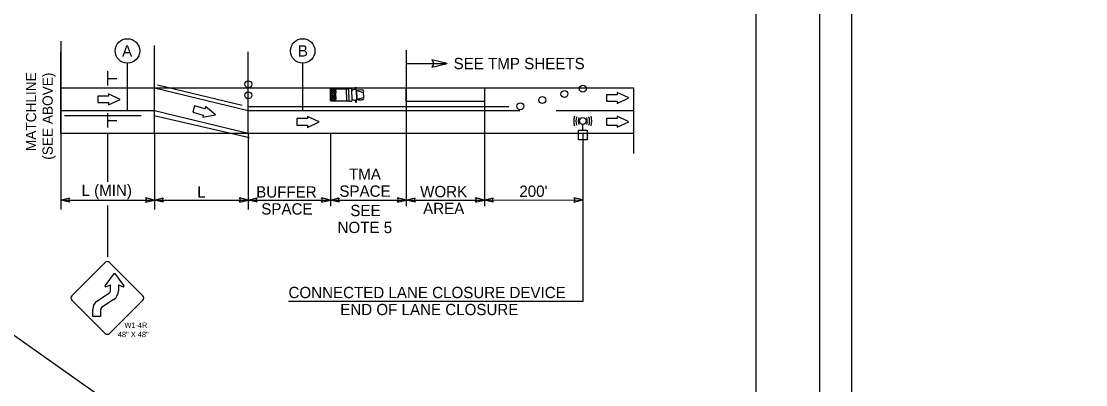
# Model space of a CAD drawing. Extents: x 1379436 to 1387057, y 792703 to 795604.
# Drawn here: x 1381631 to 1382883, y 793820 to 794247 of the extents above; entities that cross this region are included whole.
import ezdxf

# ---------------------------------------------------------------- set-up
doc = ezdxf.new("R2010")
doc.units = 0
for name, color, linetype in [('Default', 7, 'Continuous'), ('DEV BORDER CELL', 7, 'Continuous'), ('DEV DIRECTION OF TRAFFIC FLOW ARROW CELL', 7, 'Continuous'), ('DEV DRUM PLAN VIEW CELL', 7, 'Continuous'), ('DEV LINE TERMINATOR TYPE 3 CELL', 7, 'Continuous'), ('DEV TRUCK MOUNTED IMPACT ATTENUATOR CELL', 7, 'Continuous'), ('Drum Linestyle V8i', 7, 'Continuous'), ('Gray Area Fill Shapes', 7, 'Continuous'), ('Prop Mkg Skp Wht', 7, 'Continuous'), ('Prop Mkg Solid White Lane Line', 7, 'Continuous'), ('Prop Mkg Solid Yellow Edge Line', 7, 'Continuous'), ('Scratch_Level_0', 7, 'Continuous'), ('Scratch_Level_5', 7, 'Continuous'), ('Sheet Plot Border Outside CELL', 7, 'Continuous'), ('TCP Linework', 7, 'Continuous'), ('Text', 7, 'Continuous'), ('WS W1-4R CELL', 7, 'Continuous')]:
    doc.layers.add(name, color=color, linetype=linetype)

msp = doc.modelspace()

# ---------------------------------------------------------------- linework, layer by layer
at = {"layer": 'Default'}
for p, q in [((1379436.3, 795421.7), (1382883.5, 792987.4)), ((1381677.5, 794223.8), (1381677.5, 794060.7)), ((1382084.1, 794213.1), (1382084.1, 794153)), ((1382084.1, 794205.6), (1382084.1, 794142.3)), ((1381756, 794142.3), (1381756, 794198)), ((1381962.2, 794142.3), (1381962.2, 794198))]:
    msp.add_line(p, q, dxfattribs=at)
for centre in [(1381756, 794212.4), (1381962.2, 794212.4)]:
    msp.add_circle(centre, 14.4, dxfattribs=at)
at = {"layer": 'DEV BORDER CELL'}
msp.add_lwpolyline([(1382570.8, 794844.7), (1380320.7, 794844.7), (1380320.7, 793269.7), (1382570.8, 793269.7)], close=True, dxfattribs=at)
at = {"layer": 'DEV DIRECTION OF TRAFFIC FLOW ARROW CELL'}
for p, q in [((1381747.6, 794155.4), (1381733.8, 794161.9)), ((1381733.8, 794161.9), (1381733.8, 794159.2)), ((1382346, 794157), (1382332.2, 794163.5)), ((1382332.2, 794163.5), (1382332.2, 794160.9)), ((1381733.8, 794159.2), (1381721, 794159.3)), ((1381721, 794159.3), (1381721, 794151.5)), ((1381721, 794151.5), (1381733.8, 794151.5)), ((1381733.8, 794148.9), (1381747.6, 794155.4)), ((1381733.8, 794151.5), (1381733.8, 794148.9)), ((1382332.2, 794160.9), (1382319.5, 794160.9)), ((1382319.5, 794160.9), (1382319.5, 794153.2)), ((1382319.5, 794153.2), (1382332.2, 794153.2)), ((1382332.2, 794150.5), (1382346, 794157)), ((1382332.2, 794153.2), (1382332.2, 794150.5)), ((1381835, 794147.7), (1381833, 794140.3)), ((1381833, 794140.3), (1381845.3, 794136.9)), ((1381847.3, 794144.4), (1381835, 794147.7)), ((1381844.7, 794134.4), (1381859.6, 794137.1)), ((1381845.3, 794136.9), (1381844.7, 794134.4)), ((1381848, 794146.9), (1381847.3, 794144.4)), ((1381859.6, 794137.1), (1381848, 794146.9)), ((1381968, 794132.7), (1381955.2, 794132.7)), ((1381955.2, 794132.7), (1381955.2, 794125)), ((1381955.2, 794125), (1381968, 794125)), ((1381981.7, 794128.8), (1381968, 794135.3)), ((1381968, 794135.3), (1381968, 794132.7)), ((1381968, 794122.4), (1381981.7, 794128.8)), ((1381968, 794125), (1381968, 794122.4)), ((1382332.2, 794132.9), (1382319.5, 794132.9)), ((1382319.5, 794132.9), (1382319.5, 794125.2)), ((1382319.5, 794125.2), (1382332.2, 794125.2)), ((1382346, 794129.1), (1382332.2, 794135.6)), ((1382332.2, 794135.6), (1382332.2, 794132.9)), ((1382332.2, 794122.6), (1382346, 794129.1)), ((1382332.2, 794125.2), (1382332.2, 794122.6))]:
    msp.add_line(p, q, dxfattribs=at)
at = {"layer": 'DEV DRUM PLAN VIEW CELL'}
for centre in [(1381898.2, 794173.2), (1381898.2, 794173.2), (1381898.2, 794160.2), (1381898.2, 794160.2), (1382270.2, 794161.8), (1382270.2, 794161.8), (1382291.8, 794167.9), (1382291.8, 794167.9), (1382218.3, 794147.2), (1382218.3, 794147.2), (1382244.3, 794154.5), (1382244.3, 794154.5)]:
    msp.add_circle(centre, 4.08, dxfattribs=at)
at = {"layer": 'DEV LINE TERMINATOR TYPE 3 CELL'}
for points in [[(1382114.2, 794193.1), (1382132, 794197.6), (1382114.2, 794202)], [(1382114.2, 794193.1), (1382132, 794197.6), (1382114.2, 794202)], [(1381687.9, 794034.3), (1381677.5, 794036.9), (1381687.9, 794039.5)], [(1381687.9, 794034.3), (1381677.5, 794036.9), (1381687.9, 794039.5)], [(1381777.4, 794034.3), (1381787.8, 794036.9), (1381777.4, 794039.5)], [(1381777.4, 794034.3), (1381787.8, 794036.9), (1381777.4, 794039.5)], [(1381798.2, 794034.3), (1381787.8, 794036.9), (1381798.2, 794039.5)], [(1381798.2, 794034.3), (1381787.8, 794036.9), (1381798.2, 794039.5)], [(1381887.8, 794034.3), (1381898.2, 794036.9), (1381887.8, 794039.5)], [(1381887.8, 794034.3), (1381898.2, 794036.9), (1381887.8, 794039.5)], [(1381908.5, 794034.3), (1381898.2, 794036.9), (1381908.5, 794039.5)], [(1381908.5, 794034.3), (1381898.2, 794036.9), (1381908.5, 794039.5)], [(1381984.4, 794034.3), (1381994.8, 794036.9), (1381984.4, 794039.5)], [(1381984.4, 794034.3), (1381994.8, 794036.9), (1381984.4, 794039.5)], [(1382005.2, 794034.3), (1381994.8, 794036.9), (1382005.2, 794039.5)], [(1382005.2, 794034.3), (1381994.8, 794036.9), (1382005.2, 794039.5)], [(1382073.7, 794034.3), (1382084.1, 794036.9), (1382073.7, 794039.5)], [(1382073.7, 794034.3), (1382084.1, 794036.9), (1382073.7, 794039.5)], [(1382094.5, 794034.3), (1382084.1, 794036.9), (1382094.5, 794039.5)], [(1382094.5, 794034.3), (1382084.1, 794036.9), (1382094.5, 794039.5)], [(1382165.6, 794034.3), (1382176, 794036.9), (1382165.6, 794039.5)], [(1382165.6, 794034.3), (1382176, 794036.9), (1382165.6, 794039.5)], [(1382186.4, 794034.3), (1382176, 794036.9), (1382186.4, 794039.5)], [(1382186.4, 794034.3), (1382176, 794036.9), (1382186.4, 794039.5)], [(1382281.4, 794034.4), (1382291.8, 794037), (1382281.4, 794039.5)], [(1382281.4, 794034.4), (1382291.8, 794037), (1382281.4, 794039.5)]]:
    msp.add_lwpolyline(points, dxfattribs=at)
for centre, radius, start, end in [((1382110.3, 794197.6), 5.92, 311.3264, 48.6736), ((1382110.3, 794197.6), 5.92, 311.3264, 48.6736), ((1381690.1, 794036.9), 3.46, 131.3264, 228.6736), ((1381690.1, 794036.9), 3.46, 131.3264, 228.6736), ((1381775.1, 794036.9), 3.46, 311.3264, 48.6736), ((1381775.1, 794036.9), 3.46, 311.3264, 48.6736), ((1381800.5, 794036.9), 3.46, 131.3264, 228.6736), ((1381800.5, 794036.9), 3.46, 131.3264, 228.6736), ((1381885.5, 794036.9), 3.46, 311.3264, 48.6736), ((1381885.5, 794036.9), 3.46, 311.3264, 48.6736), ((1381910.8, 794036.9), 3.46, 131.3264, 228.6736), ((1381910.8, 794036.9), 3.46, 131.3264, 228.6736), ((1381982.1, 794036.9), 3.46, 311.3264, 48.6736), ((1381982.1, 794036.9), 3.46, 311.3264, 48.6736), ((1382007.5, 794036.9), 3.46, 131.3264, 228.6736), ((1382007.5, 794036.9), 3.46, 131.3264, 228.6736), ((1382071.4, 794036.9), 3.46, 311.3264, 48.6736), ((1382071.4, 794036.9), 3.46, 311.3264, 48.6736), ((1382096.8, 794036.9), 3.46, 131.3264, 228.6736), ((1382096.8, 794036.9), 3.46, 131.3264, 228.6736), ((1382163.3, 794036.9), 3.46, 311.3264, 48.6736), ((1382163.3, 794036.9), 3.46, 311.3264, 48.6736), ((1382188.7, 794036.9), 3.46, 131.3264, 228.6736), ((1382188.7, 794036.9), 3.46, 131.3264, 228.6736), ((1382279.1, 794037), 3.46, 311.3264, 48.6736), ((1382279.1, 794037), 3.46, 311.3264, 48.6736)]:
    msp.add_arc(centre, radius, start, end, dxfattribs=at)
at = {"layer": 'DEV TRUCK MOUNTED IMPACT ATTENUATOR CELL'}
for p, q in [((1381994.8, 794167.7), (1382016.6, 794167.7)), ((1381994.8, 794153.6), (1381994.8, 794167.7)), ((1381994.8, 794167.7), (1381994.8, 794165)), ((1381994.8, 794167.7), (1381994.8, 794165)), ((1381994.8, 794167.7), (1381994.8, 794165)), ((1381994.8, 794167.7), (1381994.8, 794165)), ((1381994.8, 794165), (1381994.8, 794167.7)), ((1381994.8, 794167.7), (1381997.2, 794167.7)), ((1381997.2, 794167.7), (1381994.8, 794165)), ((1381994.8, 794162.8), (1381999.2, 794167.7)), ((1382001.1, 794167.7), (1381994.8, 794160.6)), ((1381994.8, 794160.6), (1381994.8, 794162.8)), ((1381996.8, 794160.6), (1382001.1, 794165.5)), ((1382001.1, 794163.3), (1381998.7, 794160.6)), ((1381999.2, 794167.7), (1382001.1, 794167.7)), ((1382001.1, 794153.6), (1382001.1, 794167.7)), ((1382001.1, 794165.5), (1382001.1, 794163.3)), ((1382013.7, 794160.6), (1382013.7, 794167.7)), ((1382016.6, 794160.6), (1382016.6, 794167.7)), ((1382020, 794160.6), (1382020, 794167.7)), ((1382024.5, 794168.1), (1382024.5, 794169.9)), ((1382024.8, 794166.4), (1382024.8, 794169.9)), ((1382025, 794166.4), (1382025, 794169.9)), ((1382025.6, 794160.6), (1382025.6, 794165.7)), ((1382026.1, 794165.7), (1382033.7, 794163.6)), ((1382026.1, 794160.6), (1382026.1, 794165.7)), ((1382033.7, 794160.6), (1382033.7, 794163.6)), ((1381994.8, 794160.6), (1382001.1, 794153.6)), ((1381994.8, 794158.5), (1381994.8, 794160.6)), ((1381999.2, 794153.6), (1381994.8, 794158.5)), ((1381994.8, 794156.3), (1381994.8, 794153.6)), ((1381997.2, 794153.6), (1381994.8, 794156.3)), ((1381994.8, 794153.6), (1382016.6, 794153.6)), ((1381994.8, 794153.6), (1381997.2, 794153.6)), ((1382001.1, 794155.8), (1381996.8, 794160.6)), ((1381998.7, 794160.6), (1382001.1, 794158)), ((1382001.1, 794153.6), (1381999.2, 794153.6)), ((1382001.1, 794158), (1382001.1, 794155.8)), ((1382013.7, 794160.6), (1382013.7, 794153.6)), ((1382016.6, 794160.6), (1382016.6, 794153.6)), ((1382020, 794160.6), (1382020, 794153.6)), ((1382024.5, 794153.1), (1382024.5, 794151.5)), ((1382024.8, 794154.8), (1382024.8, 794151.5)), ((1382025, 794154.8), (1382025, 794151.5)), ((1382025.6, 794160.6), (1382025.6, 794155.5)), ((1382026.1, 794160.6), (1382026.1, 794155.5)), ((1382026.1, 794155.5), (1382033.7, 794157.6)), ((1382033.7, 794160.6), (1382033.7, 794157.6))]:
    msp.add_line(p, q, dxfattribs=at)
for centre in [(1382031.9, 794164.6), (1382031.9, 794156.6)]:
    msp.add_arc(centre, 2.12, 331.8801, 28.1199, dxfattribs=at)
for centre, major_axis, ratio, start_param, end_param in [((1382018.3, 794167.7), (1.67, 0), 0.269913, 0, 3.141593), ((1382022.8, 794165.4), (2.8, 0.35), 0.503092, 0, 3.141593), ((1382029.9, 794165.7), (3.82, -0.04), 0.2034, 0, 3.141593), ((1382018.3, 794153.6), (1.67, 0), 0.269913, 3.141593, 6.283185), ((1382022.8, 794155.9), (2.8, -0.35), 0.503092, 3.141593, 6.283185), ((1382029.9, 794155.6), (3.82, 0.04), 0.2034, 3.141593, 6.283185)]:
    msp.add_ellipse(centre, major_axis=major_axis, ratio=ratio, start_param=start_param, end_param=end_param, dxfattribs=at)
at = {"layer": 'Drum Linestyle V8i'}
for p, q in [((1381791.4, 794172.5), (1381891.1, 794148.4)), ((1381681.8, 794136.4), (1381772.2, 794136.5)), ((1381787.6, 794136.3), (1381899.8, 794110.3))]:
    msp.add_line(p, q, dxfattribs=at)
msp.add_lwpolyline([(1381898.2, 794146.8), (1382204.8, 794147)], dxfattribs=at)
at = {"layer": 'Gray Area Fill Shapes'}
msp.add_lwpolyline([(1382084.1, 794168.9), (1382176, 794168.9), (1382176, 794153), (1382084.1, 794153)], close=True, dxfattribs=at)
at = {"layer": 'Prop Mkg Skp Wht'}
for p, q in [((1381677.5, 794142.3), (1381677.5, 794142.3)), ((1382260.5, 794142.3), (1382351.6, 794142.3))]:
    msp.add_line(p, q, dxfattribs=at)
at = {"layer": 'Prop Mkg Solid White Lane Line'}
for p, q in [((1381677.5, 794142.3), (1381787.8, 794142.3)), ((1381787.8, 794142.3), (1381898, 794115.7)), ((1381677.5, 794115.7), (1382351.6, 794115.7))]:
    msp.add_line(p, q, dxfattribs=at)
at = {"layer": 'Prop Mkg Solid Yellow Edge Line'}
for p, q in [((1381677.5, 794168.9), (1382351.6, 794168.9)), ((1381787.8, 794168.9), (1381898.2, 794142.3)), ((1381898.2, 794142.3), (1382217.7, 794142.3))]:
    msp.add_line(p, q, dxfattribs=at)
at = {"layer": 'Scratch_Level_0'}
msp.add_line((1382351.6, 794168.9), (1382351.6, 794091.8), dxfattribs=at)
msp.add_lwpolyline([(1382495.8, 794769.7), (1380395.7, 794769.7), (1380395.7, 793344.7), (1381714, 793344.7), (1381714, 793522.1), (1382495.8, 793522.1)], close=True, dxfattribs=at)
at = {"layer": 'Scratch_Level_5'}
for p, q in [((1381787.8, 794115.7), (1381787.8, 794218.8)), ((1381677.5, 794115.7), (1381677.5, 794211.5)), ((1381898.2, 794115.7), (1381898.2, 794211.5))]:
    msp.add_line(p, q, dxfattribs=at)
at = {"layer": 'Sheet Plot Border Outside CELL'}
msp.add_lwpolyline([(1380076.3, 793232.2), (1382608.3, 793232.2), (1382608.3, 794882.2), (1380076.3, 794882.2)], close=True, dxfattribs=at)
at = {"layer": 'TCP Linework'}
for p, q in [((1381732.6, 794188.5), (1381732.6, 794171.6)), ((1381732.6, 794180), (1381743.6, 794180)), ((1381732.6, 794139), (1381732.6, 794122.1)), ((1381732.6, 794130.5), (1381743.6, 794130.5))]:
    msp.add_line(p, q, dxfattribs=at)
at = {"layer": 'Text'}
for p, q in [((1382084.1, 794197.6), (1382132, 794197.6)), ((1382233.5, 794168.9), (1382310.1, 794168.9)), ((1382084.1, 794153), (1382084.1, 794029.5)), ((1382176, 794153), (1382176, 794029.5)), ((1382291.8, 794119.3), (1382291.8, 794125.9)), ((1381677.5, 794115.7), (1381677.5, 794025.8)), ((1381732.6, 794115.7), (1381732.6, 794058.4)), ((1381787.8, 794115.7), (1381787.8, 794025.8)), ((1381898.2, 794115.7), (1381898.2, 794025.8)), ((1381994.8, 794115.7), (1381994.8, 794029.5)), ((1382291.8, 794115.7), (1382291.8, 793917.3)), ((1381677.5, 794036.9), (1381787.8, 794036.9)), ((1381787.8, 794036.9), (1381898.2, 794036.9)), ((1381822.7, 794036.9), (1381898.2, 794036.9)), ((1381898.2, 794036.9), (1381994.8, 794036.9)), ((1381994.8, 794036.9), (1382084.1, 794036.9)), ((1382084.1, 794036.9), (1382176, 794036.9)), ((1382176, 794036.9), (1382291.8, 794037)), ((1381732.6, 794030.5), (1381732.6, 793970)), ((1382291.8, 793917.3), (1381945.6, 793917.3))]:
    msp.add_line(p, q, dxfattribs=at)
msp.add_lwpolyline([(1382286.7, 794119.3), (1382296.9, 794119.3), (1382296.9, 794107.8), (1382286.7, 794107.8)], close=True, dxfattribs=at)
msp.add_circle((1382291.8, 794129.9), 3.99, dxfattribs=at)
for centre, radius, start, end in [((1382298.7, 794129.9), 17.6, 161.0657, 198.9343), ((1382298.7, 794129.9), 15, 161.0657, 198.9343), ((1382298.7, 794129.9), 12.3, 161.0657, 198.9343), ((1382284.8, 794129.9), 12.3, 341.0657, 18.9343), ((1382284.8, 794129.9), 15, 341.0657, 18.9343), ((1382284.8, 794129.9), 17.6, 341.0657, 18.9343)]:
    msp.add_arc(centre, radius, start, end, dxfattribs=at)
at = {"layer": 'WS W1-4R CELL'}
for p, q in [((1381729.8, 793935.9), (1381740.7, 793950.8)), ((1381740.7, 793950.8), (1381751.7, 793935.9)), ((1381736.2, 793936.5), (1381730.6, 793934.8)), ((1381736.2, 793930.8), (1381736.2, 793936.5)), ((1381750.9, 793934.8), (1381745.4, 793936.5)), ((1381745.4, 793936.5), (1381745.4, 793930.2)), ((1381720.7, 793918.3), (1381734.3, 793927.3)), ((1381739.8, 793919.9), (1381726.2, 793910.9)), ((1381774.2, 793919.1), (1381735, 793879.9)), ((1381715.3, 793899.7), (1381715.3, 793908.1)), ((1381724.4, 793899.7), (1381715.3, 793899.7)), ((1381724.4, 793907.4), (1381724.4, 793899.7))]:
    msp.add_line(p, q, dxfattribs=at)
for points in [[(1381690.6, 793924.3), (1381729.8, 793963.5)], [(1381735, 793963.5), (1381774.2, 793924.3)], [(1381729.8, 793879.9), (1381690.6, 793919.1)]]:
    msp.add_lwpolyline(points, dxfattribs=at)
for centre, radius, start, end in [((1381732.4, 793960.9), 3.66, 89.9935, 135), ((1381732.4, 793960.9), 3.66, 44.987, 89.9935), ((1381693.2, 793921.7), 3.66, 135, 225), ((1381730.4, 793935.5), 0.695, 143.9078, 282.5697), ((1381732, 793930.8), 4.2, 303.5775, 0), ((1381733.1, 793930.2), 12.3, 303.5774, 0), ((1381751.1, 793935.5), 0.695, 257.4303, 36.0922), ((1381771.6, 793921.7), 3.66, 315, 45), ((1381727.5, 793908.1), 12.3, 123.5774, 180), ((1381728.6, 793907.4), 4.2, 123.5772, 180), ((1381732.4, 793882.5), 3.66, 225, 270), ((1381732.4, 793882.5), 3.66, 270, 315)]:
    msp.add_arc(centre, radius, start, end, dxfattribs=at)

# ---------------------------------------------------------------- texts
at = {"layer": 'Default'}
for s, p in [('MATCHLINE', (1381648.6, 794094.5)), ('(SEE ABOVE)', (1381668.1, 794084.3))]:
    msp.add_text(s, height=12, rotation=90, dxfattribs=at).set_placement(p)
at = {"layer": 'Text'}
for s, height, p in [('A', 13.3, (1381749.7, 794205.7)), ('B', 13.3, (1381956.5, 794205.7)), ('SEE TMP SHEETS', 13.304, (1382139.8, 794190.9)), ('TMA', 13.3, (1382016.7, 794060.7)), ('L (MIN)', 13.3, (1381702, 794041.8)), ('L', 13.3, (1381838.1, 794039.8)), ('BUFFER ', 13.3, (1381907.5, 794039.8)), ('SPACE', 13.3, (1382005.4, 794040.7)), ('WORK ', 13.3, (1382100.4, 794040.2)), ("200'", 13.3, (1382217.1, 794040.6)), ('SPACE', 13.3, (1381913.5, 794019.8)), ('SEE ', 13.3, (1382018.3, 794017.9)), ('AREA', 13.3, (1382103.9, 794020.3)), ('NOTE 5', 13.3, (1382003.2, 793998)), ('CONNECTED LANE CLOSURE DEVICE', 13.304, (1381945.5, 793921.4)), ('END OF LANE CLOSURE', 13.304, (1382006.4, 793901.4))]:
    msp.add_text(s, height=height, dxfattribs=at).set_placement(p)
at = {"layer": 'WS W1-4R CELL'}
for s, height, p in [('W1-4R', 6.27, (1381752.5, 793886.4)), ("48'' X 48''", 6.273, (1381744.7, 793875.5))]:
    msp.add_text(s, height=height, dxfattribs=at).set_placement(p)

doc.saveas('drawing.dxf')
